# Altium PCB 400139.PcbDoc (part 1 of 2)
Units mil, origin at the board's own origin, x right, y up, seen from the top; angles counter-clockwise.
Board outline 2800 x 2160 mil, 2 copper layers (Top Layer, Bottom Layer), stack 61.8 mil thick; 154 components, 167 nets, 587 pads, 544 vias.
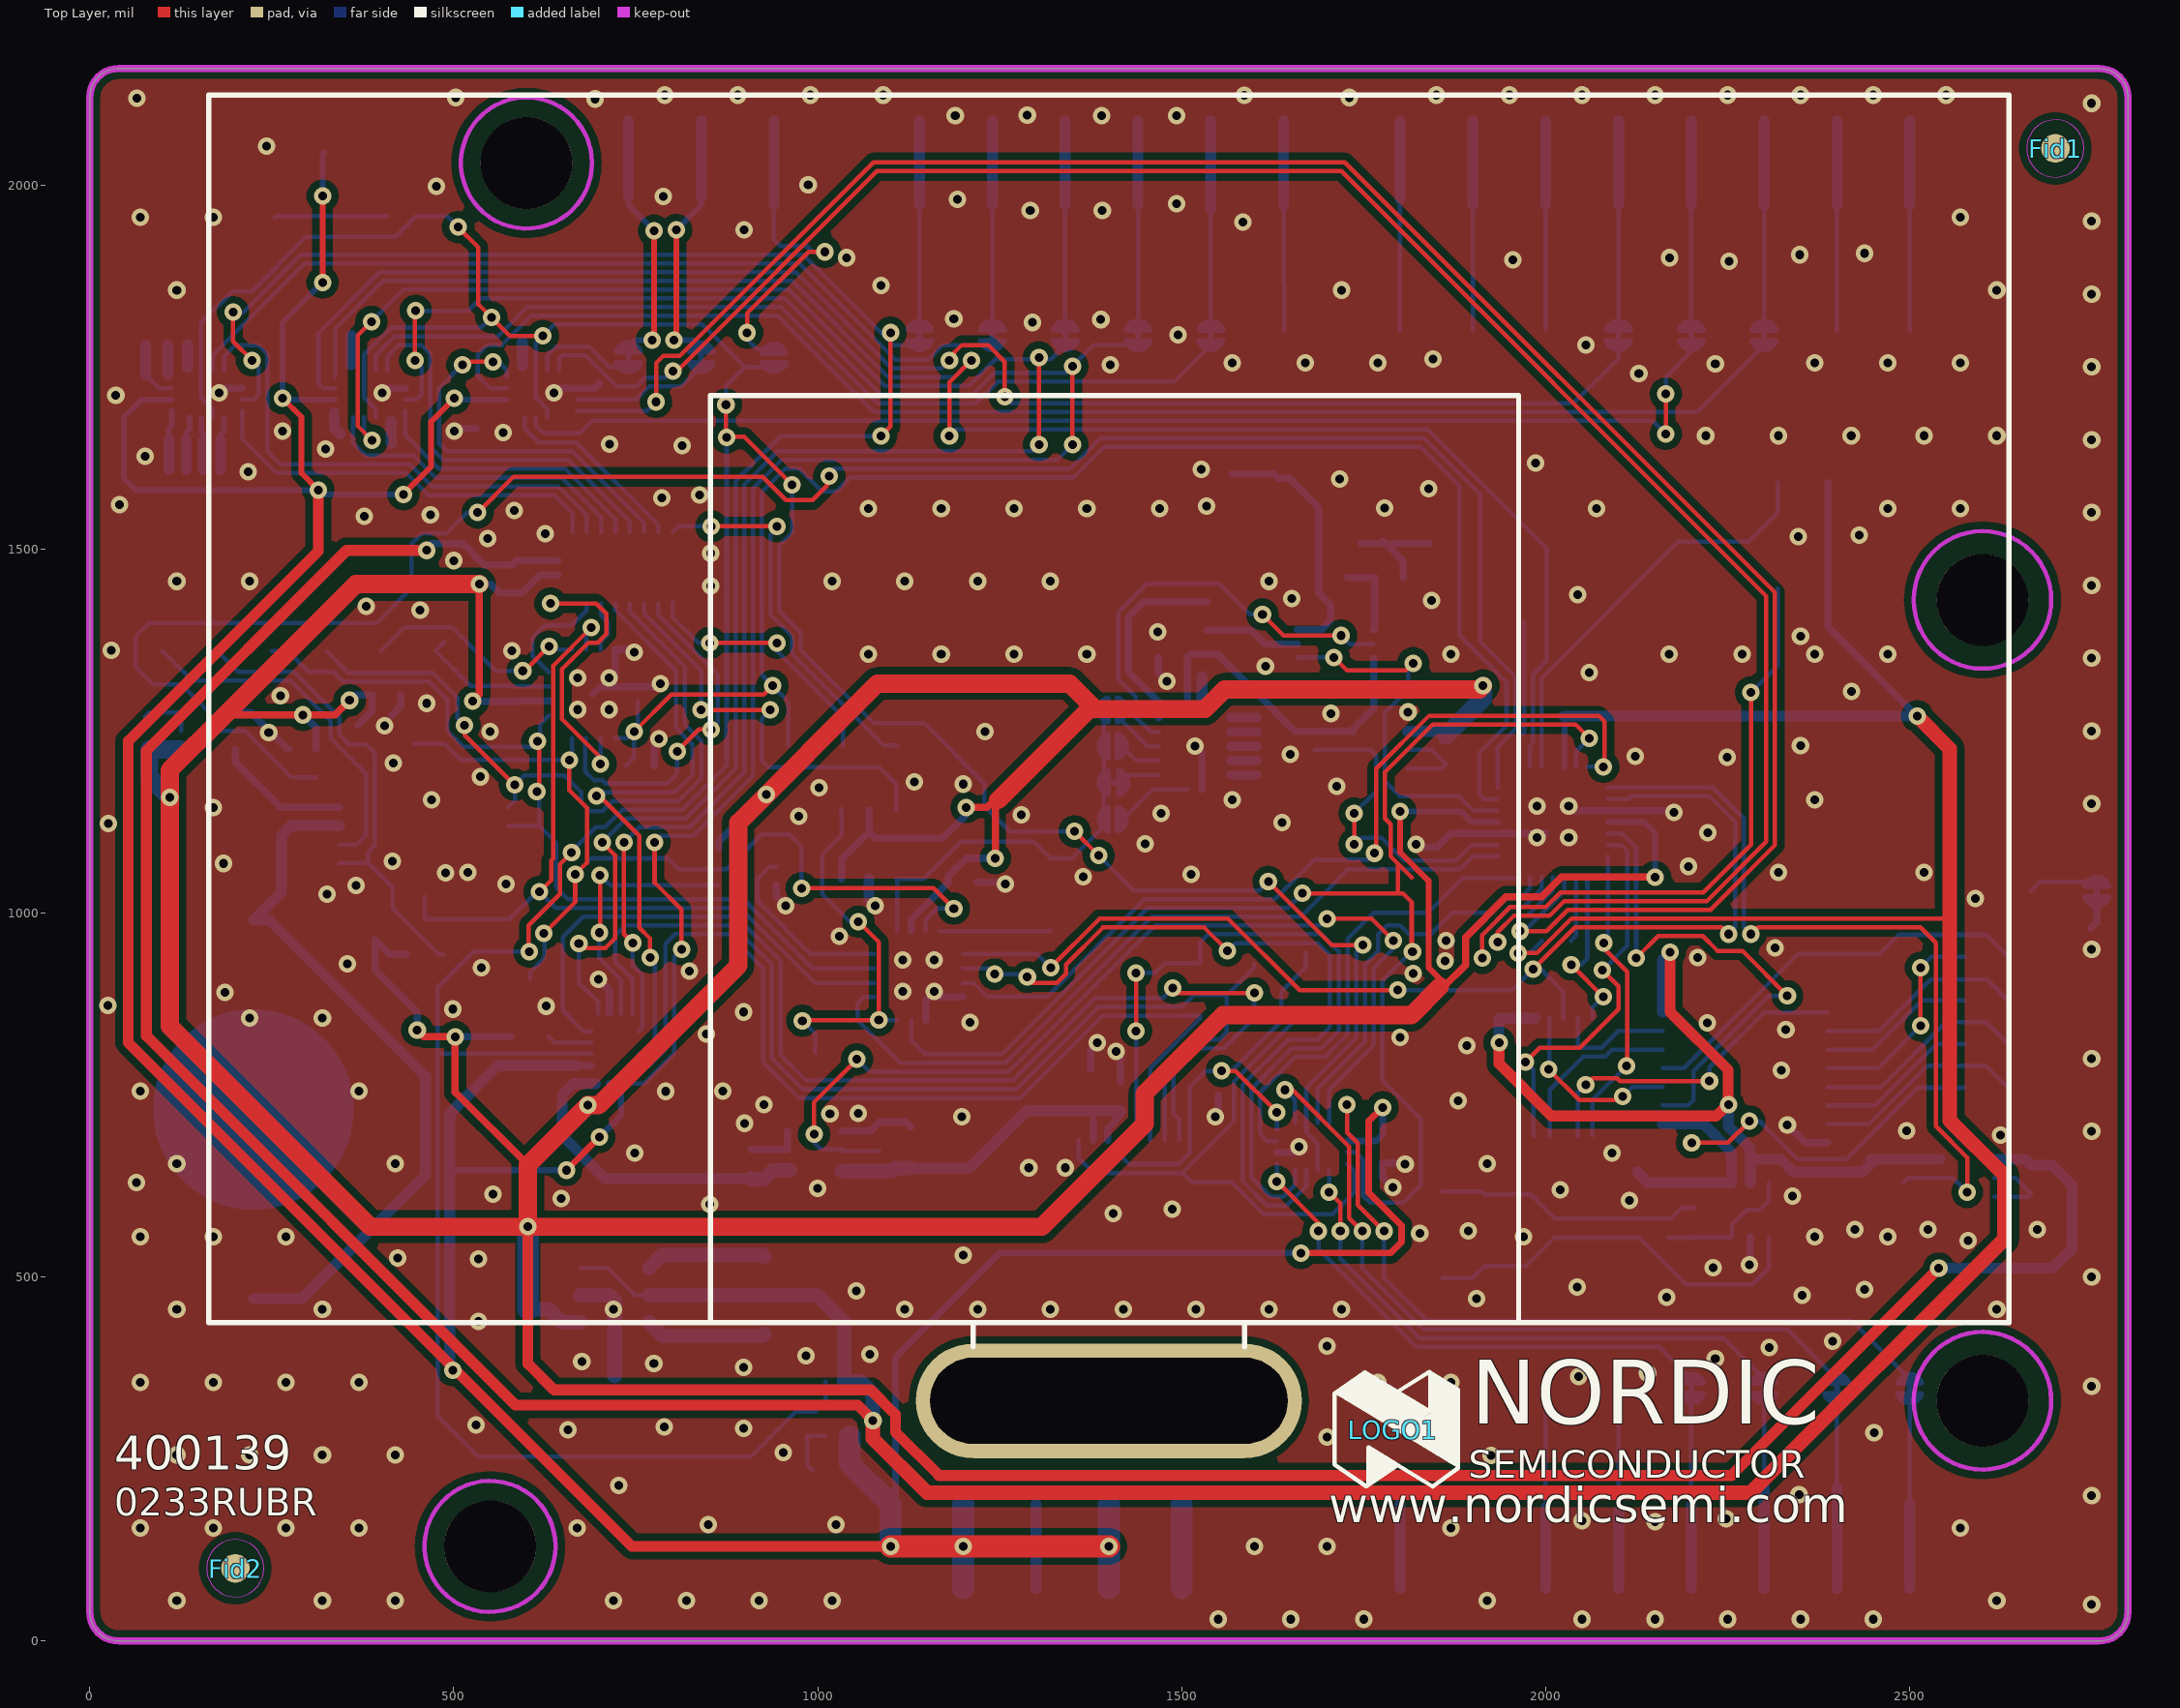
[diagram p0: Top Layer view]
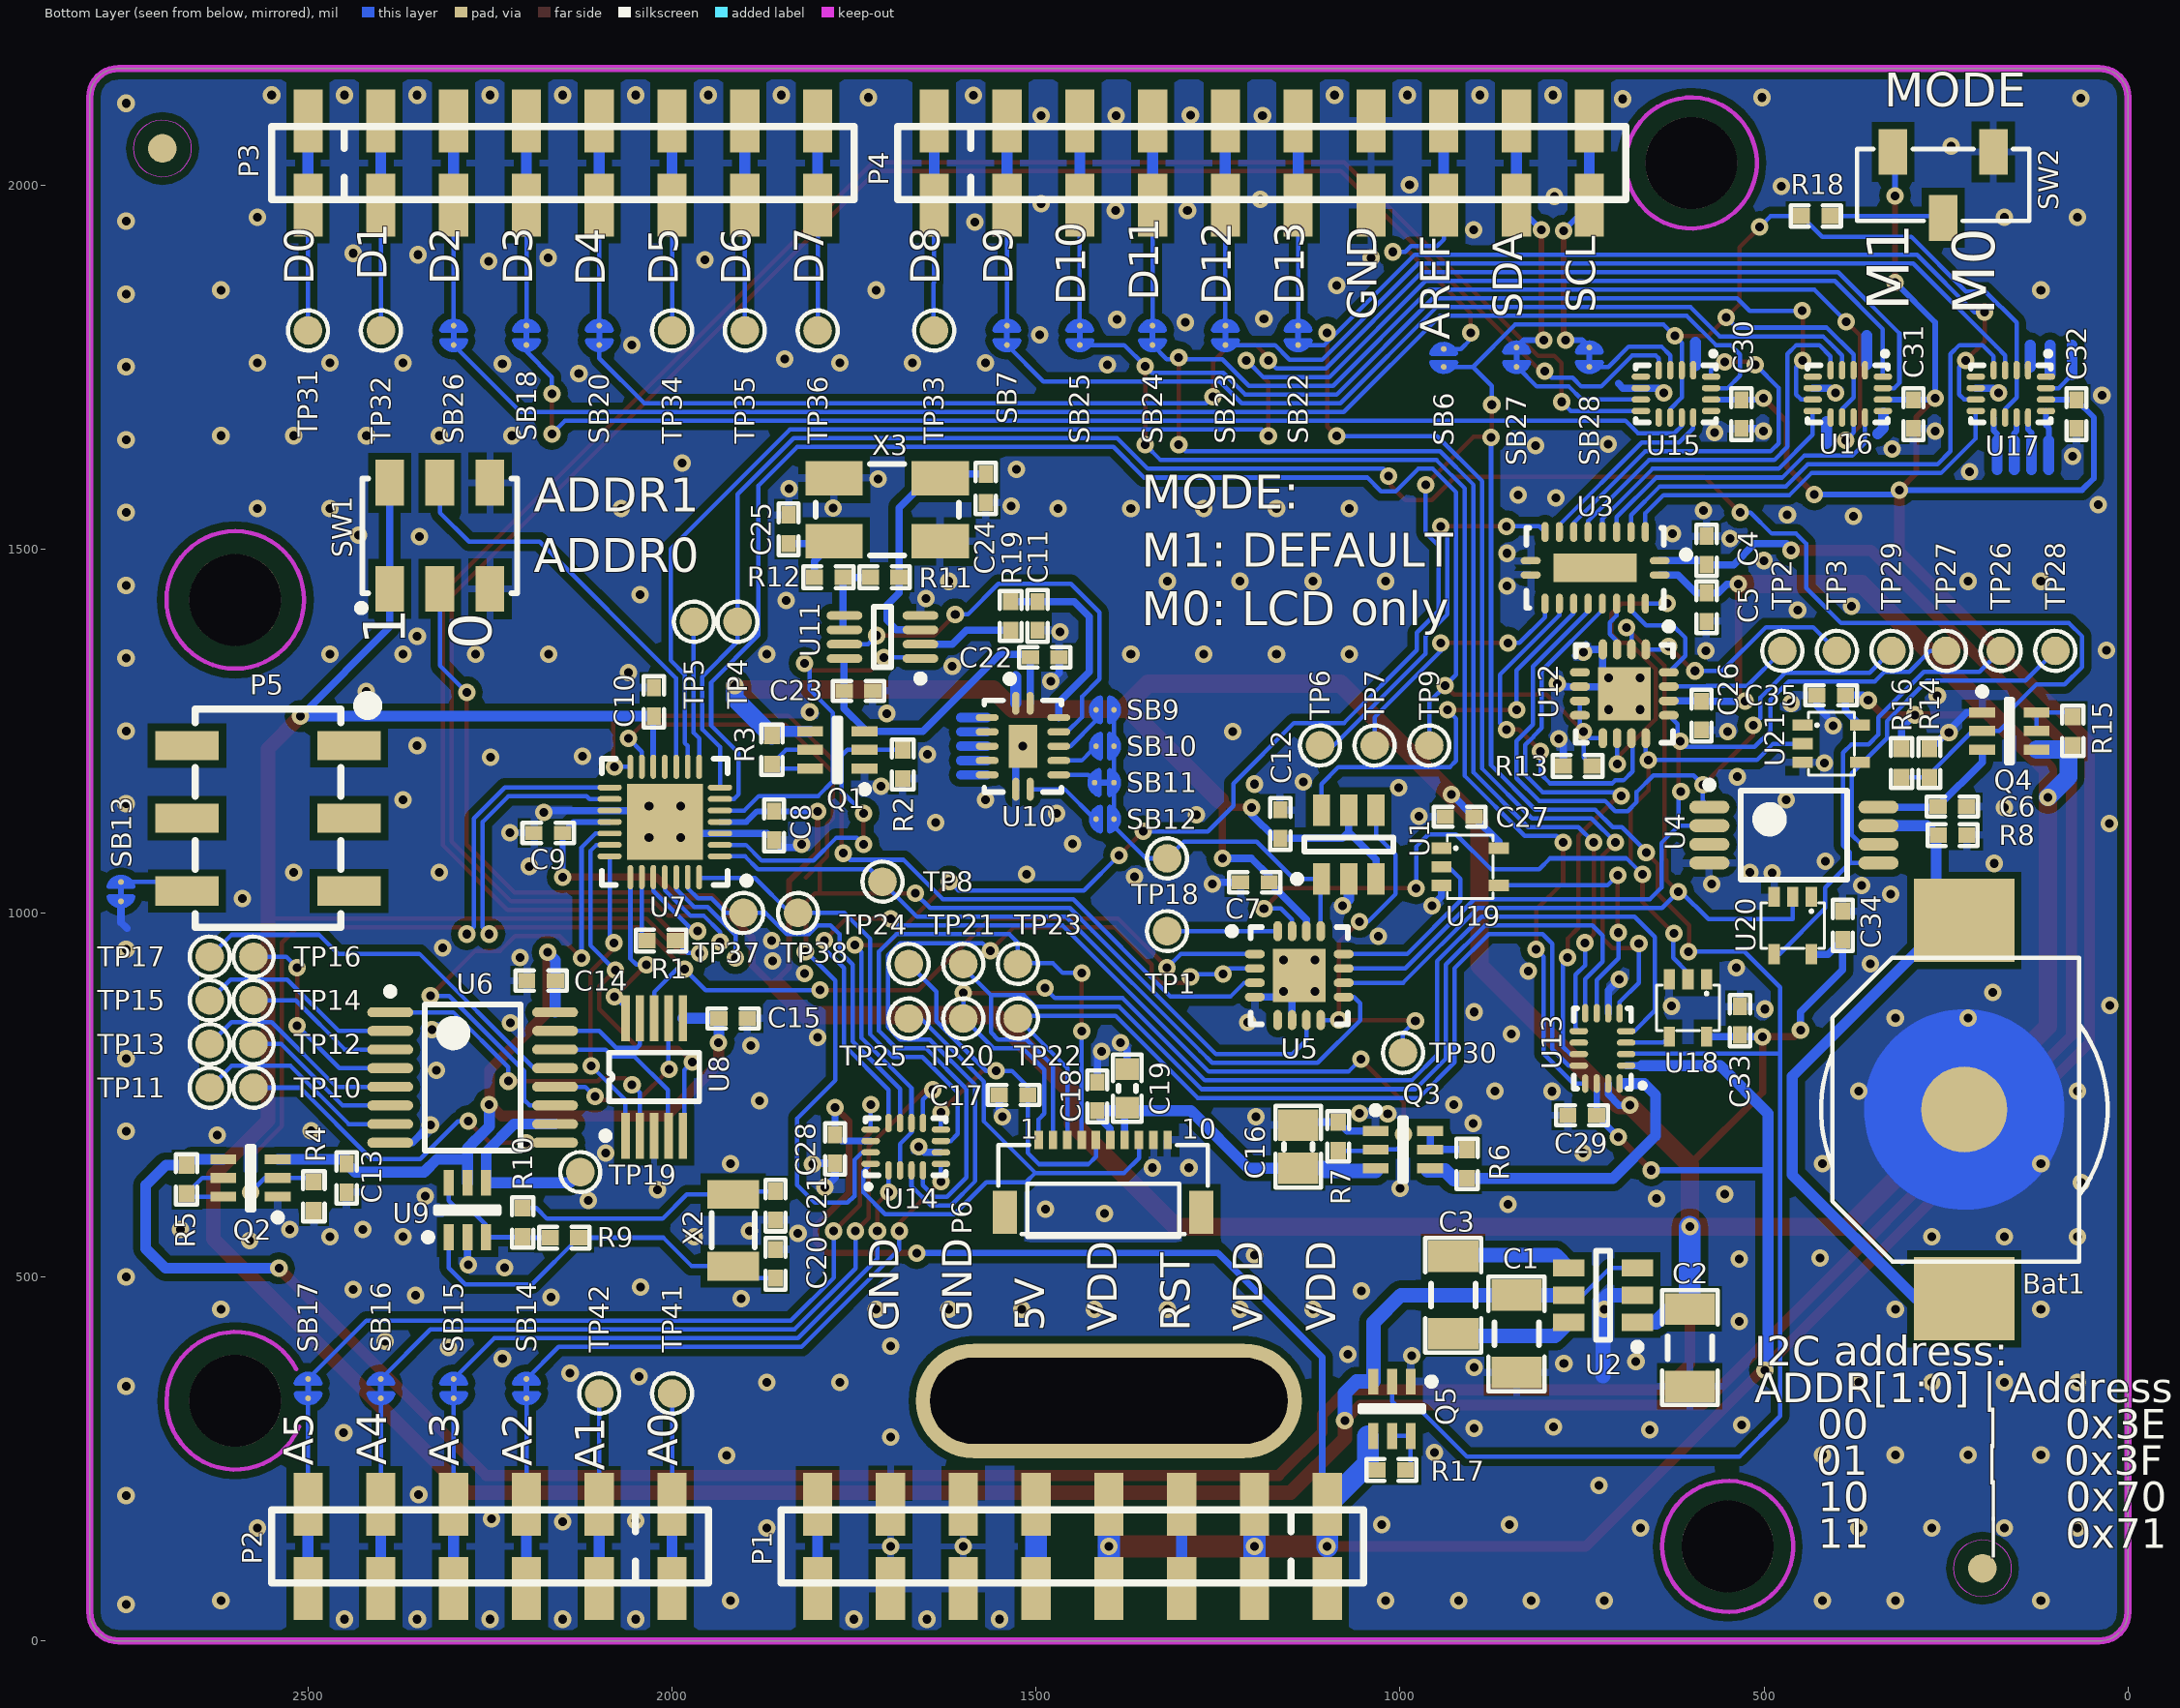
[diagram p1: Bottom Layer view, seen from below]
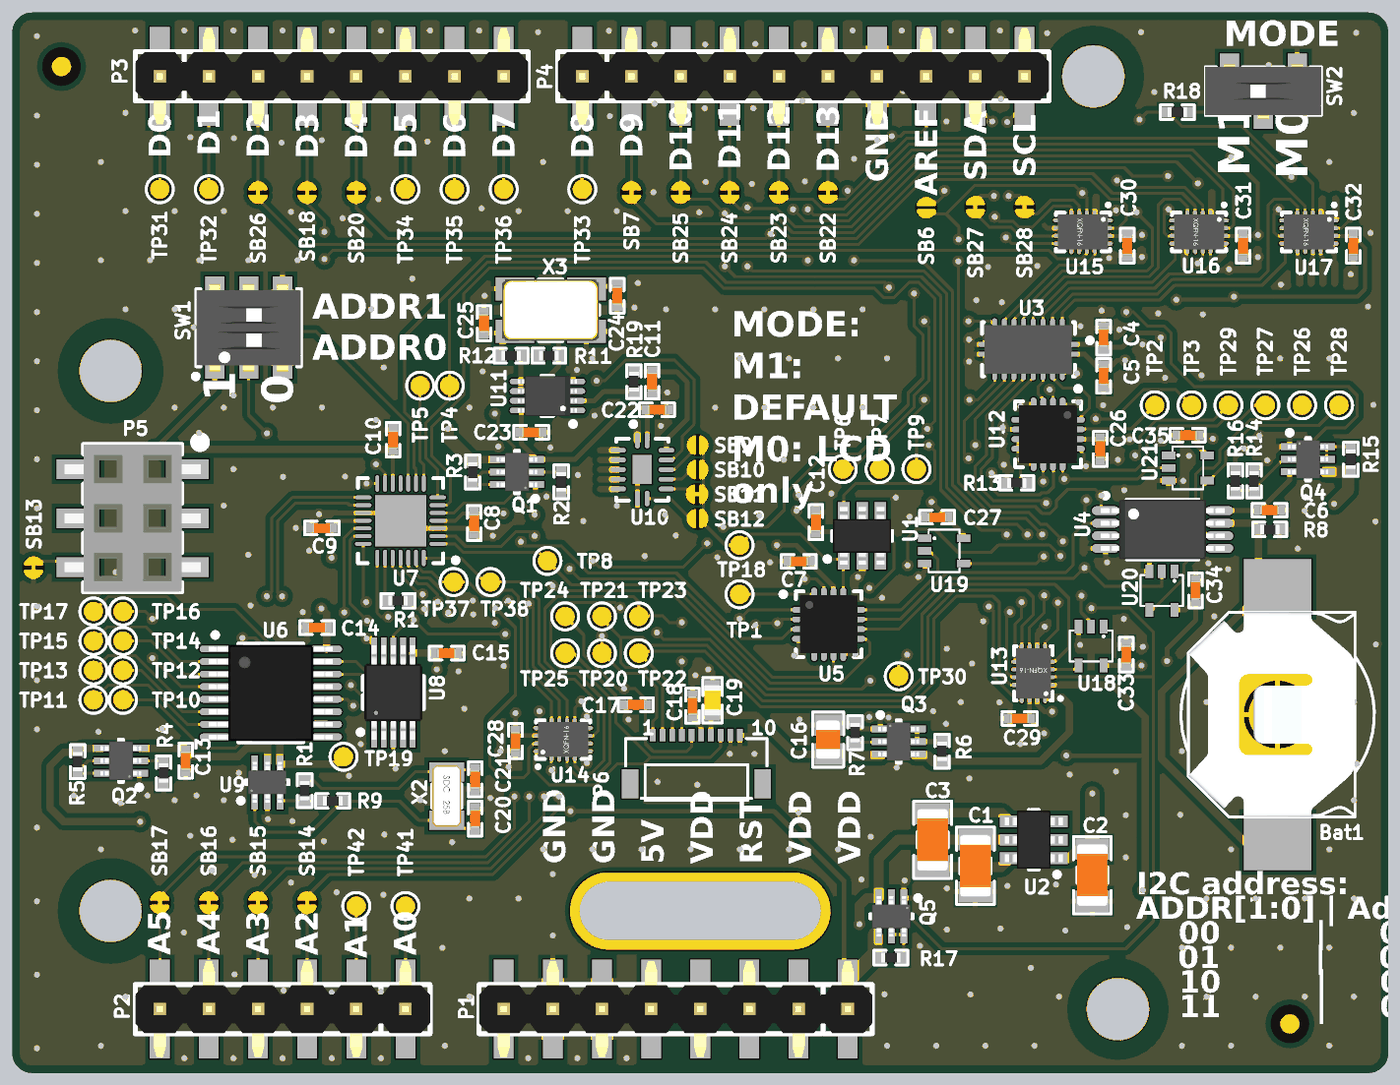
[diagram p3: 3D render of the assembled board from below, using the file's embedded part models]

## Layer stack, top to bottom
Top Solder: solder mask 0.4, Solder Resist, Dk 3.5
Top Layer: signal copper 1.4
Dielectric1: core 59, FR-4, Dk 4.4
Bottom Layer: signal copper 1.4
Bottom Solder: solder mask 0.4, Solder Resist, Dk 3.5

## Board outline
0,40 0,2120 0,2120.51 cw(c40,2120) 40.51,2160 40,2160 2760,2160 cw(c2760,2120) 2800,2120 2800,40 2800,40.51 cw(c2760,40) 2760.51,0 2760,0 40,0 cw(c40,40)

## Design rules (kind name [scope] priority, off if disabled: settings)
Clearance ANT_Clerance [InNet('ANT') or InNet('RF')] p1: gap=5
Clearance Polygon_Clearance [(InNamedPolygon('Top_Layer-GND')) or (InNamedPolygon('Bottom_Layer-GND'))] p2: gap=10
Clearance [All] p3: gap=6
ComponentClearance [All] p1 off: gap=10 collisioncheckmode=3 verticalgap=10 showdistances=FALSE
DiffPairsRouting [All] p1: maxlimit=5.91 minlimit=5.91 mostfreqgap=5.91 toplayer_minwidth=8 toplayer_maxwidth=15 toplayer_prefwidth=15 bottomlayer_minwidth=8 bottomlayer_maxwidth=15 bottomlayer_prefwidth=15 maxuncoupledlength=500
FabricationTestPointUsage TestPointUsage [All] p1: valid=0 allowmultiple=FALSE
FabricationTestpoint Testpoint [All] p1: side=3 testpointundercomponent=TRUE minsize=40 maxsize=100 preferedsize=60 minholesize=0 maxholesize=40 preferedholesize=32 testpointgrid=1 allowsidetop=TRUE allowsidebottom=TRUE usegrid=TRUE gridtolerance=0.01
Height [All] p1 off: minheight=0 maxheight=1000 prefheight=500
HoleSize [All] p1: absolutevalues=TRUE maxlimit=2000 minlimit=12 maxpercent=80.000 minpercent=20.000
MinimumAnnularRing [All] p1 off: minimumring=6
PolygonConnect PolygonConnect_1 [isVia and innet(gnd) or isVia and innet(VIO) or HasFootprint('COAXIAL-SWF')] p1: connectstyle=Direct reliefconductorwidth=10 reliefentries=4 polygonreliefangle="90 Angle" airgapwidth=10
PolygonConnect [All] p2: connectstyle=Relief reliefconductorwidth=10 reliefentries=4 polygonreliefangle="90 Angle" airgapwidth=10
RoutingVias [All] p1: holewidth=12 width=24 viastyle="Through Hole" minholewidth=12 minwidth=24 maxholewidth=28 maxwidth=50
SilkToSolderMaskClearance SilkscreenOverComponentPads [IsPad] p1: minsilkscreentomaskgap=10 clearancetoexposedcopper=TRUE
SolderMaskExpansion [All] p1: expansion=3
Width [All] p1: maxlimit=2000 minlimit=6 preferedwidth=6 minimp=50.000000 maximp=50.000000 favimp=50.000000
23 further rules are at their usual default settings.

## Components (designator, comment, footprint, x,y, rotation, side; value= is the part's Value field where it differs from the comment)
Bat1 "Bat Holder CR1025" CR1025_HOLDER_SMD 225,730 r270 bottom
C1 "2.2µF" CAPC3216X13L 840,422 r90 bottom
C2 "2.2µF" CAPC3216X13L 602,403 r90 bottom
C3 "220nF" CAPC3216X13L 927,475 r270 bottom
C4 "100nF" CAPC1005X04L 579,1498 r270 bottom
C5 "100nF" CAPC1005X04L 579,1420 r90 bottom
C6 "100nF" CAPC1005X04L 241.31,1146.16 r0 bottom
C7 "100nF" CAPC1005X04L 1199.53,1041.98 r180 bottom
C8 "100nF" CAPC1005X04L 1860,1120 r90 bottom
C9 "100nF" CAPC1005X04L 2170,1110 r180 bottom
C10 "100nF" CAPC1005X04L 2025,1290 r270 bottom
C11 "180pF" CAPC1005X04L 1498,1408 r90 bottom
C12 "100nF" CAPC1005X04L 1164.53,1121.98 r270 bottom
C13 "100nF" CAPC1005X04L 2447,636 r90 bottom
C14 "100nF" CAPC1005X04L 2179.95,907.05 r180 bottom
C15 "100nF" CAPC1005X04L 1916,855 r0 bottom
C16 "10µF" CAPC2012X11L 1139.87,679.13 r270 bottom
C17 "100nF" CAPC1005X04L 1531,750 r180 bottom
C18 "100nF" CAPC1005X04L 1415.87,748.09 r270 bottom
C19 "1.0µF" CAPC1608X06L 1374.87,759.09 r270 bottom
C20 "12pF" CAPC1005X04L 1858,518.06 r90 bottom
C21 "12pF" CAPC1005X04L 1858,598.06 r270 bottom
C22 "100nF" CAPC1005X04L 1488,1351 r0 bottom
C23 "100nF" CAPC1005X04L 1744,1305 r0 bottom
C24 "18pF" CAPC1005X04L 1569,1583 r270 bottom
C25 "18pF" CAPC1005X04L 1840,1527 r90 bottom
C26 "100nF" CAPC1005X04L 586,1271 r90 bottom
C27 "100nF" CAPC1005X04L 918,1132 r0 bottom
C28 "100nF" CAPC1005X04L 1776,676 r90 bottom
C29 "100nF" CAPC1005X04L 750,722 r180 bottom
C30 "100nF" CAPC1005X04L 531,1685 r90 bottom
C31 "100nF" CAPC1005X04L 295,1685 r90 bottom
C32 "100nF" CAPC1005X04L 71,1685 r90 bottom
C33 "100nF" CAPC1005X04L 533,852 r90 bottom
C34 "100nF" CAPC1005X04L 392,983 r90 bottom
C35 "100nF" CAPC1005X04L 408,1299 r0 bottom
Fid1 "Fiducial mark" Fiducial 2700,2050 r180 top
Fid2 "Fiducial mark" Fiducial 200,100 r0 top
LOGO1 "Nordic Logo M" NORDIC_LOGO_M 1790,290 r0 top
P1 "Pin List 1x8" LIST_1x8_SMD 1100,130 r0 bottom locked
P2 "Pin List 1x6" LIST_1x6_SMD 2000,130 r0 bottom locked
P3 "Pin List 1x8" LIST_1x8_SMD 2500,2030 r180 bottom locked
P4 "Pin List 1x10" LIST_1x10_SMD 1640,2030 r180 bottom locked
P5 "Socket 2x3" SOCKET_2x3_SMD-2.54mm-bottom 2555,1130 r270 top locked
P6 "FPC-10-0.5mm" "Molex 51441-1072" 1407.87,688.09 r0 bottom locked
Q1 "FDG6321C" SOT65P210X100-6N 1773,1224 r0 bottom
Q2 "FDG6321C" SOT65P210X100-6N 2579,636 r0 bottom
Q3 "FDG6321C" SOT65P210X100-6N 996.12,675 r180 bottom
Q4 "FDG6321C" SOT65P210X100-6N 163,1250 r180 bottom
Q5 "FDG6321C" SOT65P210X100-6N 1011,319 r270 bottom
R1 "10k" RESC1005X04L 2015,962 r180 bottom
R2 "N.C." RESC1005X04L 1683,1204 r270 bottom
R3 "1M0" RESC1005X04L 1863,1224 r270 bottom
R4 "N.C." RESC1005X04L 2492,611 r270 bottom
R5 "1M0" RESC1005X04L 2667,634 r270 bottom
R6 "1M0" RESC1005X04L 907.87,655.13 r90 bottom
R7 "N.C." RESC1005X04L 1084.87,693.13 r90 bottom
R8 "N.C." RESC1005X04L 241,1107 r0 bottom
R9 "10M" RESC1005X04L 2148,554 r0 bottom
R10 "330k" RESC1005X04L 2205,575.06 r270 bottom
R11 "1M0" RESC1005X04L 1708,1461 r0 bottom
R12 "1k" RESC1005X04L 1785,1461 r180 bottom
R13 "1M0" RESC1005X04L 756,1202 r180 bottom
R14 "N.C." RESC1005X04L 273,1206 r90 bottom
R15 "1M0" RESC1005X04L 76,1250 r90 bottom
R16 "1M0" RESC1005X04L 311,1206 r270 bottom
R17 "1M0" RESC1005X04L 1012,235 r180 bottom
R18 "10k" RESC1005X04L 429,1957 r180 bottom
R19 "100R" RESC1005X04L 1535,1408 r90 bottom
SB6 "Solderbridge" Solderbridge#1 940,1750 r90 bottom
SB7 "Solderbridge" Solderbridge_Shorted 1540,1780 r90 bottom net-tie
SB9 "Solderbridge" Solderbridge#2 1393,1279 r0 bottom
SB10 "Solderbridge" Solderbridge#2 1393,1229 r0 bottom
SB11 "Solderbridge" Solderbridge_Shorted 1393,1179 r0 bottom net-tie
SB12 "Solderbridge" Solderbridge#3 1393,1129 r0 bottom
SB13 "Solderbridge" Solderbridge_Shorted 2757,1016 r90 bottom net-tie
SB14 "Solderbridge" Solderbridge_Shorted 2200,360 r270 bottom net-tie
SB15 "Solderbridge" Solderbridge_Shorted 2300,360 r270 bottom net-tie
SB16 "Solderbridge" Solderbridge_Shorted 2400,360 r270 bottom net-tie
SB17 "Solderbridge" Solderbridge_Shorted 2500,360 r270 bottom net-tie
SB18 "Solderbridge" Solderbridge_Shorted 2200,1780 r90 bottom net-tie
SB20 "Solderbridge" Solderbridge_Shorted 2100,1780 r90 bottom net-tie
SB22 "Solderbridge" Solderbridge_Shorted 1140,1780 r90 bottom net-tie
SB23 "Solderbridge" Solderbridge_Shorted 1240,1780 r90 bottom net-tie
SB24 "Solderbridge" Solderbridge_Shorted 1340,1780 r90 bottom net-tie
SB25 "Solderbridge" Solderbridge_Shorted 1440,1780 r90 bottom net-tie
SB26 "Solderbridge" Solderbridge_Shorted 2300,1780 r90 bottom net-tie
SB27 "Solderbridge" Solderbridge_Shorted 840,1750 r90 bottom net-tie
SB28 "Solderbridge" Solderbridge_Shorted 740,1750 r90 bottom net-tie
SW1 "Switch" CAS-D20A 2319,1518 r180 bottom
SW2 "Switch" CJS-120xA 254,2000 r0 bottom
TP1 "Ø1.0mm,SMD" TP_SMD_Ø1.0mm#1 1320,975 r180 bottom
TP2 "Ø1.0mm,SMD" TP_SMD_Ø1.0mm#1 475,1360 r180 bottom
TP3 "Ø1.0mm,SMD" TP_SMD_Ø1.0mm#1 400,1360 r180 bottom
TP4 "Ø1.0mm,SMD" TP_SMD_Ø1.0mm#1 1910,1400 r180 bottom
TP5 "Ø1.0mm,SMD" TP_SMD_Ø1.0mm#1 1970,1400 r180 bottom
TP6 "Ø1.0mm,SMD" TP_SMD_Ø1.0mm#1 1110,1230 r180 bottom
TP7 "Ø1.0mm,SMD" TP_SMD_Ø1.0mm#1 1035,1230 r180 bottom
TP8 "Ø1.0mm,SMD" TP_SMD_Ø1.0mm#1 1711,1043 r180 bottom
TP9 "Ø1.0mm,SMD" TP_SMD_Ø1.0mm#1 960,1230 r180 bottom
TP10 "Ø1.0mm,SMD" TP_SMD_Ø1.0mm#1 2575,760 r180 bottom
TP11 "Ø1.0mm,SMD" TP_SMD_Ø1.0mm#1 2635,760 r180 bottom
TP12 "Ø1.0mm,SMD" TP_SMD_Ø1.0mm#1 2575,820 r180 bottom
TP13 "Ø1.0mm,SMD" TP_SMD_Ø1.0mm#1 2635,820 r180 bottom
TP14 "Ø1.0mm,SMD" TP_SMD_Ø1.0mm#1 2575,880 r180 bottom
TP15 "Ø1.0mm,SMD" TP_SMD_Ø1.0mm#1 2635,880 r180 bottom
TP16 "Ø1.0mm,SMD" TP_SMD_Ø1.0mm#1 2575,940 r180 bottom
TP17 "Ø1.0mm,SMD" TP_SMD_Ø1.0mm#1 2635,940 r180 bottom
TP18 "Ø1.0mm,SMD" TP_SMD_Ø1.0mm#1 1320,1075 r180 bottom
TP19 "Ø1.0mm,SMD" TP_SMD_Ø1.0mm#1 2126,644.06 r180 bottom
TP20 "Ø1.0mm,SMD" TP_SMD_Ø1.0mm#1 1600,855 r180 bottom
TP21 "Ø1.0mm,SMD" TP_SMD_Ø1.0mm#1 1600,930 r180 bottom
TP22 "Ø1.0mm,SMD" TP_SMD_Ø1.0mm#1 1525,855 r180 bottom
TP23 "Ø1.0mm,SMD" TP_SMD_Ø1.0mm#1 1525,930 r180 bottom
TP24 "Ø1.0mm,SMD" TP_SMD_Ø1.0mm#1 1675,930 r180 bottom
TP25 "Ø1.0mm,SMD" TP_SMD_Ø1.0mm#1 1675,855 r180 bottom
TP26 "Ø1.0mm,SMD" TP_SMD_Ø1.0mm#2 150,1360 r180 bottom
TP27 "Ø1.0mm,SMD" TP_SMD_Ø1.0mm#1 250,1360 r180 bottom
TP28 "Ø1.0mm,SMD" TP_SMD_Ø1.0mm#1 100,1360 r180 bottom
TP29 "Ø1.0mm,SMD" TP_SMD_Ø1.0mm#1 325,1360 r180 bottom
TP30 "Ø1.0mm,SMD" TP_SMD_Ø1.0mm#1 996,808 r180 bottom
TP31 "Ø1.0mm,SMD" TP_SMD_Ø1.0mm#1 2500,1800 r180 bottom
TP32 "Ø1.0mm,SMD" TP_SMD_Ø1.0mm#1 2400,1800 r180 bottom
TP33 "Ø1.0mm,SMD" TP_SMD_Ø1.0mm#1 1640,1800 r180 bottom
TP34 "Ø1.0mm,SMD" TP_SMD_Ø1.0mm#1 2000,1800 r180 bottom
TP35 "Ø1.0mm,SMD" TP_SMD_Ø1.0mm#1 1900,1800 r180 bottom
TP36 "Ø1.0mm,SMD" TP_SMD_Ø1.0mm#1 1800,1800 r180 bottom
TP37 "Ø1.0mm,SMD" TP_SMD_Ø1.0mm#1 1902,1000 r180 bottom
TP38 "Ø1.0mm,SMD" TP_SMD_Ø1.0mm#1 1827,1000 r180 bottom
TP41 "Ø1.0mm,SMD" TP_SMD_Ø1.0mm#1 2000,340 r180 bottom
TP42 "Ø1.0mm,SMD" TP_SMD_Ø1.0mm#1 2100,340 r180 bottom
U1 "SN74LVC1G175" SOT95P280X145-6N 1070.53,1093.98 r90 bottom
U2 "REG710NA-3.3" SOT95P280X145-6N 721.16,475 r0 bottom
U3 "FXMA108" QFN50P450X250X80_HS-21N 732,1474 r270 bottom
U4 "23LCV512" TSOP65P640X120-8N 459,1107 r180 bottom
U5 "NX3L4053" QFN50P300X300X50_HS-17N 1138.53,913.98 r180 bottom
U6 "74VHC4040FT" TSOP65P640X110-16N 2273.95,774.05 r180 bottom
U7 "SX1509BIULTRT" QFN40P400X400X60_HS-29N 2010,1125 r0 bottom
U8 "ADG704" MSOP-10 2063.95,694.05 r180 bottom
U9 "74LVC2GU04" SOT65P210X100-6N 2281,592.06 r90 bottom
U10 "74HC393BQ" QFN50P250X300X100_HS-15N 1518,1229 r180 bottom
U11 "74LVC3GU04DC" TSSOP50P310X90-8N 1711,1379 r0 bottom
U12 "NX3L4053" QFN50P300X300X50_HS-17N 692,1301 r270 bottom
U13 "NX3DV2567" XQFN40P180X260X50-16N 722,814 r0 bottom
U14 "FSA2466UMX" XQFN40P180X260X50-16N 1679,679 r90 bottom
U15 "FSA2466UMX" XQFN40P180X260X50-16N 621,1713 r270 bottom
U16 "FSA2466UMX" XQFN40P180X260X50-16N 385,1713 r270 bottom
U17 "FSA2466UMX" XQFN40P180X260X50-16N 161,1713 r270 bottom
U18 "74LVC1G17" SOT-353 579,909 r0 bottom
U19 "74LVC1G17" SOT-353 943,1089 r270 bottom
U20 "74LVC1G17" SOT-353 435,1022 r0 bottom
U21 "74LVC1G17" SOT-353 447,1258 r270 bottom
X2 "32.768kHz" XTAL_3215 1916,564.06 r270 bottom
X3 "8MHz" BT-XTAL_5032 1704.47,1553.75 r0 bottom

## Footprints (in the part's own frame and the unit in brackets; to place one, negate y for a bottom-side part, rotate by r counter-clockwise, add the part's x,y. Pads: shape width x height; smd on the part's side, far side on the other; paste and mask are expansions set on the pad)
BT-XTAL_5032 [mm] "Abracon ABM3B Series 5.0mmx3.2mm SMD"
  rect 2x1.2 smd: 1(-1.85,-1.1) 2(1.85,-1.1) 3(1.85,1.1) 4(-1.85,1.1)
  silkscreen extent -2.5,-1.6 2.5,1.6, body extent -2.5,-1.6 2.5,1.6, height 1
CAPC1005X04L [mm] "Chip Capacitor, 2-Leads, Body 1.0x0.5mm, IPC High Density"
  rect 0.6x0.5 smd: 1(-0.5,0) 2(0.5,0)
  silkscreen extent -0.9,-0.35 0.9,0.35, body extent -0.51,-0.25 0.51,0.25, height 0.5
CAPC1608X06L [mm] "Chip Capacitor, 2-Leads, Body 1.6x0.8mm, IPC High Density"
  rect 0.75x0.8 smd: 1(-0.675,0) 2(0.675,0)
  silkscreen extent -1.17,-0.5 1.17,0.5, body extent -0.8,-0.43 0.8,0.43, height 0.8
CAPC2012X11L [mm] "Chip Capacitor, 2-Leads, Body 2.0x1.3mm, IPC High Density"
  rect 1.1x1.4 smd: 1(-0.75,0) 2(0.75,0)
  silkscreen extent -1.43,-0.8 1.42,0.8, body extent -1,-0.62 1,0.63, height 0.77
CAPC3216X13L [mm] "Chip Capacitor, 2-Leads, Body 3.2x1.6mm, IPC High Density"
  rect 1.1x1.75 smd: 1(-1.35,0) 2(1.35,0)
  silkscreen extent -2,-0.97 2,0.97, body extent -1.6,-0.8 1.6,0.8, height 0.99
CAS-D20A [mm] "SLIDE SWITCH 2xSPDT J HOOK"
  rect 1x1.6 smd: 1(-1.75,-1.85) 2(0,-1.85) 3(1.75,-1.85) 4(-1.75,1.85) 5(0,1.85) 6(1.75,1.85)
  silkscreen extent -2.84,-2.62 2.7,2, body extent -2.7,-2.27 2.7,2.28, height 2.5
CJS-120xA [mm] "Slide Switches - SPDT, SMD, ON-ON"
  rect 1x1.6 smd: 1(1.75,-1.15) 2(0,1.15) 3(-1.75,-1.15)
  silkscreen extent -3,-1.25 3,1.25, body extent -3,-1.4 3,1.45, height 2.5
CR1025_HOLDER_SMD [mm] "CR1025 battery retainer SMD"
  round 7 on Bottom Solder paste+0: 0(0,0)
  rect 2.9x3.5 smd: 1(-6.6,0) 1(6.6,0)
  round 3 smd paste-8: 2(0,0)
  Top Layer circle w5: c0,0 r1
  silkscreen extent -5.3,-5 5.3,5, body extent -8.05,-4.61 8.05,4, height 1.95
Fiducial [mm] "Fiducial Mark"
  round 1 smd paste-10 mask+0.5: 0(0,0)
  round 1 smd far side paste-10 mask+0.5: 0(0,0)
  Keep-Out Layer circle w0.01: c0,0 r1
LIST_1x6_SMD [mm] "Pin List, 2.54mm, SMD"
  rect 1.02x2.19 smd: 1(0,-1.465) 1(0,1.465) 2(2.54,-1.465) 2(2.54,1.465) 3(5.08,-1.465) 3(5.08,1.465) 4(7.62,-1.465) 4(7.62,1.465) 5(10.16,-1.465) 5(10.16,1.465) 6(12.7,-1.465) 6(12.7,1.465)
  silkscreen extent -1.27,-1.27 13.97,1.27, body extent -1.27,-2.5 13.97,2.5, height 9.82
LIST_1x8_SMD [mm] "Pin List, 2.54mm, SMD"
  rect 1.02x2.19 smd: 1(0,-1.465) 1(0,1.465) 2(2.54,-1.465) 2(2.54,1.465) 3(5.08,-1.465) 3(5.08,1.465) 4(7.62,-1.465) 4(7.62,1.465) 5(10.16,-1.465) 5(10.16,1.465) 6(12.7,-1.465) 6(12.7,1.465) 7(15.24,-1.465) 7(15.24,1.465) 8(17.78,-1.465) 8(17.78,1.465)
  silkscreen extent -1.27,-1.27 19.05,1.27, body extent -1.27,-2.5 19.05,2.5, height 9.82
LIST_1x10_SMD [mm] "Pin List, 2.54mm, SMD"
  rect 1.02x2.19 smd: 1(0,-1.465) 1(0,1.465) 2(2.54,-1.465) 2(2.54,1.465) 3(5.08,-1.465) 3(5.08,1.465) 4(7.62,-1.465) 4(7.62,1.465) 5(10.16,-1.465) 5(10.16,1.465) 6(12.7,-1.465) 6(12.7,1.465) 7(15.24,-1.465) 7(15.24,1.465) 8(17.78,-1.465) 8(17.78,1.465) 9(20.32,-1.465) 9(20.32,1.465) 10(22.86,-1.465) 10(22.86,1.465)
  silkscreen extent -1.27,-1.27 24.13,1.27, body extent -1.27,-2.5 24.13,2.5, height 9.82
"Molex 51441-1072" [mm] "Connector, FPC, SMD, 0.5mm, 10-way"
  rect 0.3x0.65 smd mask+0.076: 1(2.25,0) 2(1.75,0) 3(1.25,0) 4(0.75,0) 5(0.25,0) 6(-0.25,0) 7(-0.75,0) 8(-1.25,0) 9(-1.75,0) 10(-2.25,0)
  rect 0.85x1.5 smd: ""(-3.425,2.525) ""(3.425,2.525)
  silkscreen extent -3.65,0.18 3.65,3.37
MSOP-10 [mm] "Shrink Small Outline; 10 Leads; Body Width 3 mm; Pitch 0.5 mm"
  rect 0.3x1.6 smd: 1(0,0) 2(0.5,0) 3(1,0) 4(1.5,0) 5(2,0) 6(2,4.1) 7(1.5,4.1) 8(1,4.1) 9(0.5,4.1) 10(0,4.1)
  silkscreen extent -0.83,-0.12 2.58,2.9, body extent -0.5,-0.4 2.5,4.5, height 1.15
NORDIC_LOGO_M [mil] "Medium Nordic Logo"
  silkscreen extent -80,-78 90,80
QFN40P400X400X60_HS-29N [mm] "QFN, 28-Leads, Body 4,00x4,00mm, Pitch 0,40mm, Thermal Pad 2,65x2,65mm, IPC Medium Density"
  oval 0.85x0.2 smd: 1(-1.925,1.2) 2(-1.925,0.8) 3(-1.925,0.4) 4(-1.925,0) 5(-1.925,-0.4) 6(-1.925,-0.8) 7(-1.925,-1.2) 15(1.925,-1.2) 16(1.925,-0.8) 17(1.925,-0.4) 18(1.925,0) 19(1.925,0.4) 20(1.925,0.8) 21(1.925,1.2)
  oval 0.2x0.85 smd: 8(-1.2,-1.925) 9(-0.8,-1.925) 10(-0.4,-1.925) 11(0,-1.925) 12(0.4,-1.925) 13(0.8,-1.925) 14(1.2,-1.925) 22(1.2,1.925) 23(0.8,1.925) 24(0.4,1.925) 25(0,1.925) 26(-0.4,1.925) 27(-0.8,1.925) 28(-1.2,1.925)
  rect 2.65x2.65 smd: 29(0,0)
  silkscreen extent -2.97,-2.2 2.2,2.2, body extent -2.05,-2.05 2.05,2.05, height 0.6
QFN50P250X300X100_HS-15N [mm] "QFN, 14-Leads, Body 2.50x3.00mm, Pitch 0.50mm, Thermal Pad 1.00x1.50mm, IPC Medium Density"
  oval 0.25x0.8 smd: 1(-0.25,1.5) 7(-0.25,-1.5) 8(0.25,-1.5) 14(0.25,1.5)
  oval 0.8x0.25 smd: 2(-1.25,1) 3(-1.25,0.5) 4(-1.25,0) 5(-1.25,-0.5) 6(-1.25,-1) 9(1.25,-1) 10(1.25,-0.5) 11(1.25,0) 12(1.25,0.5) 13(1.25,1)
  rect 1x1.5 smd: 15(0,0)
  silkscreen extent -1.35,-1.6 1.35,2.47, body extent -1.3,-1.55 1.3,1.55, height 1
QFN50P300X300X50_HS-17N [mm] "QFN, 16-Leads, Body 3.00x3.00mm, Pitch 0.50mm, Thermal Pad 1.85x1.85mm, IPC Medium Density"
  oval 0.7x0.3 smd: 1(-1.55,0.75) 2(-1.55,0.25) 3(-1.55,-0.25) 4(-1.55,-0.75) 9(1.55,-0.75) 10(1.55,-0.25) 11(1.55,0.25) 12(1.55,0.75)
  oval 0.3x0.7 smd: 5(-0.75,-1.55) 6(-0.25,-1.55) 7(0.25,-1.55) 8(0.75,-1.55) 13(0.75,1.55) 14(0.25,1.55) 15(-0.25,1.55) 16(-0.75,1.55)
  rect 1.85x1.85 smd: 17(0,0)
  silkscreen extent -2.48,-1.7 1.7,1.7, body extent -1.5,-1.5 1.5,1.5, height 0.9
QFN50P450X250X80_HS-21N [mm] "QFN, 20-Leads, Body 4.50x2.50mm, Pitch 0.50mm, Thermal Pad 3.15x1.15mm, IPC Medium Density"
  oval 0.25x0.7 smd: 1(-0.25,2.25) 10(-0.25,-2.25) 11(0.25,-2.25) 20(0.25,2.25)
  oval 0.7x0.25 smd: 2(-1.25,1.75) 3(-1.25,1.25) 4(-1.25,0.75) 5(-1.25,0.25) 6(-1.25,-0.25) 7(-1.25,-0.75) 8(-1.25,-1.25) 9(-1.25,-1.75) 12(1.25,-1.75) 13(1.25,-1.25) 14(1.25,-0.75) 15(1.25,-0.25) 16(1.25,0.25) 17(1.25,0.75) 18(1.25,1.25) 19(1.25,1.75)
  rect 1x2.9 smd: 21(0,0)
  silkscreen extent -1.4,-2.4 1.4,3.29, body extent -1.25,-2.27 1.27,2.25, height 1
RESC1005X04L [mm] "Chip Resistor, 2-Leads, Body 1.0x0.5mm, IPC High Density"
  rect 0.6x0.55 smd: 1(-0.5,0) 2(0.5,0)
  silkscreen extent -0.87,-0.38 0.88,0.38, body extent -0.5,-0.25 0.5,0.25, height 0.3
SOCKET_2x3_SMD-2.54mm-bottom [mm] "Socket, 2.54mm, SMD"
  rect 1.02x2.22 smd far side: 1(-2.54,-2.825) 2(-2.54,2.825) 3(0,-2.825) 4(0,2.825) 5(2.54,-2.825) 6(2.54,2.825)
  body extent -3.81,-3.52 3.81,3.52, height 7.47
Solderbridge#1 [mm]
  round 0.2 smd paste-10: 1(0,0) 2(0.625,0)
  Top Layer region: 0.389,0.432 0.465,0.505 0.583,0.467 0.648,0.424 0.721,0.351 0.775,0.292 0.833,0.193 0.861,0.099 0.856,-0.122 0.831,-0.193 0.747,-0.33 0.663,-0.411 0.571,-0.469 0.47,-0.5 0.419,-0.483 0.389,-0.43
  Top Layer region: 0.236,-0.432 0.16,-0.505 0.042,-0.467 -0.023,-0.424 -0.097,-0.351 -0.15,-0.292 -0.208,-0.193 -0.236,-0.099 -0.231,0.122 -0.206,0.193 -0.122,0.33 -0.038,0.411 0.054,0.469 0.155,0.5 0.206,0.483 0.236,0.43
  Top Layer lines w0.152: 0.159,-0.431 cw(c0.27,0) 0,-0.353 cw(c0.27,0) 0.159,0.431 ; 0.465,-0.431 ccw(c0.355,0) 0.625,-0.353 ccw(c0.355,0) 0.465,0.431
Solderbridge#2 [mm]
  round 0.2 smd paste-10: 1(0,0) 2(0.625,0)
  Top Layer region: 0.389,0.432 0.465,0.505 0.583,0.467 0.648,0.424 0.721,0.351 0.775,0.292 0.833,0.193 0.861,0.099 0.856,-0.122 0.831,-0.193 0.747,-0.33 0.663,-0.411 0.571,-0.469 0.47,-0.5 0.419,-0.483 0.389,-0.43
  Top Layer region: 0.236,-0.432 0.16,-0.505 0.042,-0.467 -0.023,-0.424 -0.097,-0.351 -0.15,-0.292 -0.208,-0.193 -0.236,-0.099 -0.231,0.122 -0.206,0.193 -0.122,0.33 -0.038,0.411 0.054,0.469 0.155,0.5 0.206,0.483 0.236,0.43
  Top Layer lines w0.152: 0.159,0.431 ccw(c0.27,0) 0.159,-0.431 ; 0.465,0.431 cw(c0.355,0) 0.465,-0.431
Solderbridge#3 [mm]
  round 0.2 smd paste-10: 1(0,0) 2(0.625,0)
  Top Layer region: 0.389,0.432 0.465,0.505 0.583,0.467 0.648,0.424 0.721,0.351 0.775,0.292 0.833,0.193 0.861,0.099 0.856,-0.122 0.831,-0.193 0.747,-0.33 0.663,-0.411 0.571,-0.469 0.47,-0.5 0.419,-0.483 0.389,-0.43
  Top Layer region: 0.236,-0.432 0.16,-0.505 0.042,-0.467 -0.023,-0.424 -0.097,-0.351 -0.15,-0.292 -0.208,-0.193 -0.236,-0.099 -0.231,0.122 -0.206,0.193 -0.122,0.33 -0.038,0.411 0.054,0.469 0.155,0.5 0.206,0.483 0.236,0.43
  Top Layer lines w0.152: 0.159,0.431 ccw(c0.27,0) 0,0.353 ccw(c0.27,0) -0.052,0.306 ccw(c0.27,0) 0,-0.353 ccw(c0.27,0) 0.159,-0.431 ; 0.465,0.431 cw(c0.355,0) 0.465,-0.431
Solderbridge_Shorted [mm]
  round 0.2 smd paste-10: 1(0,0) 2(0.676,0)
  Top Layer region: 0.236,-0.432 0.16,-0.505 0.042,-0.467 -0.023,-0.424 -0.097,-0.351 -0.15,-0.292 -0.208,-0.193 -0.236,-0.099 -0.231,0.122 -0.206,0.193 -0.122,0.33 -0.038,0.411 0.054,0.469 0.155,0.5 0.206,0.483 0.236,0.43
  Top Layer region: 0.44,0.432 0.516,0.505 0.634,0.467 0.699,0.424 0.772,0.351 0.826,0.292 0.884,0.193 0.912,0.099 0.907,-0.122 0.881,-0.193 0.798,-0.33 0.714,-0.411 0.622,-0.469 0.521,-0.5 0.47,-0.483 0.44,-0.43
  Top Layer lines w0.152: 0.159,-0.431 cw(c0.27,0) 0.159,0.431 ; 0.516,-0.431 ccw(c0.406,0) 0.516,0.431
  Top Layer lines w0.203: 0,0 0.676,0
SOT65P210X100-6N [mm] "SOT23, 6-Leads, Body 2,2x2,4mm (max), Pitch 0,65mm, IPC Medium Density"
  rect 0.9x0.35 smd: 1(-0.95,0.65) 2(-0.95,0) 3(-0.95,-0.65) 4(0.95,-0.65) 5(0.95,0) 6(0.95,0.65)
  silkscreen extent -1.07,-1.1 0.1,1.5, body extent -1.05,-1 1.05,1, height 0.92
SOT95P280X145-6N [mm] "SOT23, 6-Leads, Body 3,1x3,0mm (max), Pitch 0,95mm, IPC Medium Density"
  rect 1.1x0.6 smd: 1(-1.2,0.95) 2(-1.2,0) 3(-1.2,-0.95) 4(1.2,-0.95) 5(1.2,0) 6(1.2,0.95)
  silkscreen extent -1.32,-1.55 0.25,1.93, body extent -1.5,-1.5 1.5,1.5, height 1.45
SOT-353 [mm]
  rect 0.4x0.7 smd: 1(0,0) 2(0.65,0) 3(1.3,0) 4(1.3,2) 5(0,2)
  silkscreen extent -0.45,0.2 1.75,1.8
TP_SMD_Ø1.0mm#1 [mm]
  round 1 smd paste-5: 1(0,0)
  silkscreen extent -0.7,-0.7 0.7,0.7
TP_SMD_Ø1.0mm#2 [mm]
  round 1 smd paste-5: 1(-0.635,0)
  silkscreen extent -1.34,-0.7 0.06,0.7
TSOP65P640X110-16N [mm] "TSOP, 16-Leads, Body 5.00x4.40mm, Pitch 0.65mm, IPC Medium Density"
  oval 1.6x0.35 smd: 1(-2.875,2.275) 2(-2.875,1.625) 3(-2.875,0.975) 4(-2.875,0.325) 5(-2.875,-0.325) 6(-2.875,-0.975) 7(-2.875,-1.625) 8(-2.875,-2.275) 9(2.875,-2.275) 10(2.875,-1.625) 11(2.875,-0.975) 12(2.875,-0.325) 13(2.875,0.325) 14(2.875,0.975) 15(2.875,1.625) 16(2.875,2.275)
  silkscreen extent -3,-2.55 1.68,3.12, body extent -3.2,-2.5 3.2,2.5, height 1
TSOP65P640X120-8N [mm] "TSOP, 8-Leads, Body 3.00x4.40mm, Pitch 0.65mm, IPC Medium Density"
  oval 1.4x0.45 smd: 1(-2.95,0.975) 2(-2.95,0.325) 3(-2.95,-0.325) 4(-2.95,-0.975) 5(2.95,-0.975) 6(2.95,-0.325) 7(2.95,0.325) 8(2.95,0.975)
  silkscreen extent -3.08,-1.55 1.85,1.87, body extent -3.2,-1.55 3.2,1.55, height 1.2
TSSOP50P310X90-8N [mm] "TSSOP, 8-Leads, Body 2,1x2,4mm (max), Pitch 0,50mm, IPC Medium Density"
  oval 1.25x0.3 smd: 1(-1.325,0.75) 2(-1.325,0.25) 3(-1.325,-0.25) 4(-1.325,-0.75) 5(1.325,-0.75) 6(1.325,-0.25) 7(1.325,0.25) 8(1.325,0.75)
  silkscreen extent -1.45,-1.05 0.3,1.57, body extent -1.55,-1.05 1.55,1.05, height 0.8
XQFN40P180X260X50-16N [mm] "QFN, 16-Leads, Body 1.80x2.60mm, Pitch 0.40mm, IPC Medium Density"
  oval 0.65x0.22 smd paste-0.02 mask+0.062: 1(-0.825,0.6) 2(-0.825,0.2) 3(-0.825,-0.2) 4(-0.825,-0.6) 9(0.825,-0.6) 10(0.825,-0.2) 11(0.825,0.2) 12(0.825,0.6)
  oval 0.22x0.65 smd paste-0.02 mask+0.062: 5(-0.6,-1.225) 6(-0.2,-1.225) 7(0.2,-1.225) 8(0.6,-1.225) 13(0.6,1.225) 14(0.2,1.225) 15(-0.2,1.225) 16(-0.6,1.225)
  silkscreen extent -1.45,-1.4 1,1.4, body extent -0.91,-1.31 0.91,1.31, height 0.55
XTAL_3215 [mm] "XTAL SMD 3.2 x 1.5 mm"
  rect 1x1.8 smd: 1(-1.25,0) 2(1.25,0)
  silkscreen extent -0.6,-0.75 0.6,0.75, body extent -1.6,-0.75 1.6,0.75, height 0.81

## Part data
Bat1: library part "Bat Holder CR1025 SMD", "Bat Holder CR1025 SMD"
C1 C2: library part C1206-2µ2, "Capacitor, X7R, ±10%"
C3: library part C0805-220n, "Capacitor, X7R, ±10%"
C4 C5 C6 C7 C8 C9 C10 C12 C13 C14 C15 C17 C18 C22 C23 C26 C27 C28 C29 C30 C31 C32 C33 C34 C35: library part C0402-100n, "Capacitor, X7R, ±10%"
C11: library part C0402-180p, "Capacitor, NP0, ±5%"
C16: library part C0805-10µ, "Capacitor, X5R, ±10%"
C19: library part C0603-1µ0, "Capacitor, X7R, ±10%"
C20 C21: library part C0402-12p, "Capacitor, NP0, ±2%"
C24 C25: library part C0402-18p, "Capacitor, NP0, ±5%"
Fid1 Fid2: library part Fid-Mark, "Fiducial Mark"
LOGO1: "Nordic Logo, medium size"
P1 P3: library part "Pin List 1x8 SMD", "Pin List 1x8, 2.54mm (100mil), SMD"
P2: library part "Pin List 1x6 SMD", "Pin List 1x6, 2.54mm (100mil), SMD"
P4: library part "Pin List 1x10 SMD", "Pin List 1x10, 2.54mm (100mil), SMD"
P5: library part "Socket 2x3 SMD Bottom", "Socket 2x3, 2.54mm (100mil), SMD"
P6: library part "Molex 51441-1072", "FFC/FPC Connector, Right-Angle, SMD, ZIF, Bottom Contacts, 10-way, Gold"
Q1 Q2 Q3 Q4 Q5: "Fairchild, FDG6321C, Dual N & P Channel Digital FET"
R1 R18: library part R0402-10k, "Resistor, ±1%, 0.063W"
R2 R4 R7 R8 R14: library part R0402-N.C., "Not mounted"
R3 R5 R6 R11 R13 R15 R16 R17: library part R0402-1M0, "Resistor, ±1%, 0.063W"
R9: library part R0402-10M, "Resistor, ±1%, 0.063W"
R10: library part R0402-330k, "Resistor, ±1%, 0.063W"
R12: library part R0402-1K0, "Resistor, ±1%, 0.063W"
R19: library part R0402-100, "Resistor, ±1%, 0.063W"
SB7 SB11 SB13 SB14 SB15 SB16 SB17 SB18 SB20 SB22 SB23 SB24 SB25 SB26 SB27 SB28: library part "Solderbridge Shorted", "Shorted Solderbridge"
SW1: library part CAS-D20TA, "SMD slide Switch 2xSPDT"
SW2: library part CJS-1200TA, "SMD slide Switch (ON-ON)"
TP1 TP2 TP3 TP4 TP5 TP6 TP7 TP8 TP9 TP10 TP11 TP12 TP13 TP14 TP15 TP16 TP17 TP18 TP19 TP20 TP21 TP22 TP23 TP24 TP25 TP26 TP27 TP28 TP29 TP30 TP31 TP32 TP33 TP34 TP35 TP36 TP37 TP38 TP41 TP42: library part TP_SMD_Ø1.0MM, "1.0mm circular SMD testpad"
U1: library part SN74LVC1G175DBVR, "Single D-Type Flip-Flop With Asynchronous Clear"
U2: "IC MULTI CONFG 3.3V 30MA SOT23-6"
U3: library part FXMA108BQX, "8-bit bidirectional voltage-level translator with auto-direction sensing"
U4: library part 23LCV512-I/ST, "512 kbit SPI Serial SRAM with Battery Backup and SDI Interface"
U5 U12: library part NX3L4053HR, "Triple low-ohmic single-pole double-throw analog switch"
U6: "12-Stage Ripple Carry Binary Counter"
U7: "IC GPIO EXPANDER I2C 16CH 28QFN"
U8: library part ADG704BRMZ, "IC MUX 4-CH 1.8/5.5V 10MSOP"
U9: "Dual Inverter"
U10: "Dual 4-bit binary ripple counter"
U11: library part 74LVC3GU04DC,125, "Triple Inverter"
U13: library part NX3DV2567GU, "Low-ohmic four-pole double-throw analog switch"
U14 U15 U16 U17: "Data / Audio Low-Voltage Dual DPDT Analog Switch"
U18 U19 U20 U21: library part 74LVC1G17SE, "Single schmitt-trigger buffer with standard push-pull output"
X2: library part "XTAL_FC-135 32.768k", "EPSON TOYOCOM - FC-135 32.768KHZ ±20PPM,9.0PF - CRYSTAL, SM, WATCH"
X3: library part XTAL_SMD5032_8MHz_18pF_TXC, "XTAL SMD 5032, 8MHz, Cl=18pF, Tol: ±30ppm, Stab: ±30ppm"

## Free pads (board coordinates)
  oval 530.32x157.48 hole 118.11 slot 490.94 at 0 deg: 0(1400,330)
  round 126 hole 126: 1(550,130) 1(600,2030) 1(2600,330) 1(2600,1430)

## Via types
v1: diameter 24, hole 12, Top Layer to Bottom Layer, tented both sides, 544 vias

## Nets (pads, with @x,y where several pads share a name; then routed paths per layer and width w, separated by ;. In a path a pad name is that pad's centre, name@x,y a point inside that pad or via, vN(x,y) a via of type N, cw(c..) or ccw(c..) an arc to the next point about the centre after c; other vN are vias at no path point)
1C\P\: U10.1 | length 36.4
  Bottom Layer w15: U10.1@1527.84,1288.06 1527.84,1324.47
1MHZ: SB11.2 U10.9 | length 55.6
  Bottom Layer w6: SB11.2@1417.6,1179 1423.46,1184.86 1428.23,1189.63 U10.9@1468.79,1189.63
1MR: U10.2 | length 36.4
  Bottom Layer w13: U10.2@1567.21,1268.37 1603.63,1268.37
1Q0: U10.3 | length 36.4
  Bottom Layer w13: U10.3@1567.21,1248.68 1603.63,1248.68
1Q1: U10.4 | length 36.4
  Bottom Layer w13: U10.4@1567.21,1229 1603.63,1229
1Q2: U10.5 | length 36.4
  Bottom Layer w13: U10.5@1567.21,1209.31 1603.63,1209.31
1Q3: U10.6 | length 36.4
  Bottom Layer w13: U10.6@1567.21,1189.63 1603.63,1189.63
2MHZ: SB10.2 U10.10 | length 59.3
  Bottom Layer w6: SB10.2@1417.6,1229 1423.46,1223.14 1437.29,1209.31 U10.10@1468.79,1209.31
4MHZ: SB9.2 U10.11 | length 80.5
  Bottom Layer w6: SB9.2@1417.6,1279 1417.6,1265.1 1417.6,1264.4 1453,1229 U10.11@1468.79,1229
8HZ: U6.1 U8.2 | length 462.4
  Top Layer w6: v1(2054.95,764.05) 2063.95,773.05 2098.25,773.05 2102.3,769 v1(2225,769)
  Bottom Layer w6: U8.2@2044.26,694.05 2044.26,753.36 v1(2054.95,764.05) ; v1(2225,769) 2225,788.06 2300.56,863.61 U6.1@2387.13,863.61
16HZ: U6.15 U8.9 | length 164.2
  Bottom Layer w6: U8.9@2044.26,855.47 2044.26,819 2048.29,814.97 2076.97,814.97 2100.02,838.02 U6.15@2160.76,838.02
32HZ: U6.14 U8.4 | length 241.2
  Bottom Layer w6: U8.4@2004.89,694.05 2005.95,695.1 2005.95,757.05 2051.87,802.97 2081.94,802.97 2091.4,812.43 U6.14@2160.76,812.43
64HZ: U6.12 U8.7 | length 252.4
  Top Layer w6: v1(2003.95,785.35) 2046.25,743.05 2101.05,743.05 v1(2106,748)
  Bottom Layer w6: v1(2003.95,785.35) 2004.89,786.29 U8.7@2004.89,855.47 ; v1(2106,748) 2119.25,761.25 U6.12@2160.76,761.25
500KHZ: SB12.2 U10.8 | length 105.5
  Bottom Layer w6: SB12.2@1419.6,1129 1460.54,1169.94 U10.8@1508.16,1169.94
A0: P2.1 TP41.1 | length 267.7
  Bottom Layer w6: P2.1@2000,183 TP41.1@2000,340
  Bottom Layer w15: P2.1@2000,72.32 P2.1@2000,183
A1: P2.2 TP42.1 | length 267.7
  Bottom Layer w6: P2.2@2100,179 TP42.1@2100,340
  Bottom Layer w15: P2.2@2100,72.32 P2.2@2100,179
A2: SB14.1 U14.5 | length 726.8
  Top Layer w6: v1(1630.77,631.23) 1688,574 v1(1688,563)
  Bottom Layer w6: v1(1630.77,631.23) U14.5@1630.77,655.38 ; v1(1688,563) 1688,538 1822,404 2156,404 SB14.1@2200,360
A3: SB15.1 U14.1 | length 778.3
  Top Layer w6: v1(1702.62,616.62) 1718,601.24 v1(1718,563)
  Bottom Layer w6: v1(1702.62,616.62) U14.1@1702.62,646.52 ; v1(1718,563) 1718,524.97 1826.97,416 2244,416 SB15.1@2300,360
A4: SB16.1 U14.9 | length 1060.8
  Top Layer w6: v1(1642,757) 1652,757 1730,679 1730,581 v1(1748,563)
  Bottom Layer w6: v1(1642,757) 1655.38,743.62 U14.9@1655.38,711.48 ; v1(1748,563) 1748,511.94 1831.94,428 2332,428 SB16.1@2400,360
A5: SB17.1 U14.13 | length 1072.6
  Top Layer w6: v1(1727.23,736.77) 1727.23,698.74 1742,683.97 1742,599 v1(1778,563)
  Bottom Layer w6: U14.13@1727.23,702.62 v1(1727.23,736.77) ; v1(1778,563) 1778,498.91 1836.91,440 2420,440 SB17.1@2500,360
ADDR0: SW1.2 U7.26 | length 974.2
  Top Layer w6: v1(1913,938) 1913,969.67 1951.33,1008 2000.12,1008 2020.43,1028.31 2216.31,1028.31 2282,1094 v1(2282,1303)
  Bottom Layer w6: v1(1913,938) 1913,969.67 1951.33,1008 1969.6,1008 1994.25,1032.65 U7.26@1994.25,1049.21 ; v1(2282,1303) 2319,1340 SW1.2@2319,1445.17
ADDR1: SW1.5 U7.10 | length 581.4
  Bottom Layer w6: U7.10@1994.25,1200.79 1994.25,1322.25 2182,1510 2279,1510 2319,1550 SW1.5@2319,1590.83
AREF: Q5.2 R18.1 SB6.1 U13.2 U14.2 U14.10 U15.2 U15.10 U16.2 U16.10 U17.2 U17.10 | length 5765.3
  Top Layer w6: v1(506,1942) 534,1914 534,1835.87 v1(551.87,1818) 577.37,1792.5 v1(622.5,1792.5) ; v1(604,947) 603,948 603,983 646,1026 646,1067 v1(662,1083) ; v1(874,1698) 874,1654 899,1654 v1(965,1588) ; v1(1353,1112) v1(1386,1079) ; v1(1619,1043) 1706,956 v1(1749,956)
  Bottom Layer w6: U17.10@168.87,1680.52 168.87,1692.09 153.13,1707.84 U17.2@153.13,1745.48 153.13,1810.82 196,1853.7 222.79,1853.7 297.59,1928.5 420.19,1928.5 R18.1@448.69,1957 491,1957 v1(506,1942) ; U16.10@392.87,1680.52 392.87,1692.09 377.13,1707.84 U16.2@377.13,1745.48 377.13,1767.1 414.03,1804 537.87,1804 v1(551.87,1818) ; v1(604,947) 527,947 478,898 478,806.24 ; U15.10@628.87,1680.52 628.87,1692.09 613.13,1707.84 U15.2@613.13,1745.48 613.13,1783.13 v1(622.5,1792.5) 638,1808 842,1808 900,1750 ; v1(662,1083) 662,1084.7 695.3,1118 708.03,1118 732.03,1142 814.03,1142 875,1202.97 v1(875,1653) ; U13.2@689.52,806.13 688.77,806.88 478.88,806.88 478.76,807 478,806.24 ; v1(874,1698) 874,1724 900,1750 ; SB6.1@940,1750 926.1,1750 900,1750 ; v1(965,1588) 965,1522.3 947,1504.3 947,1414.97 977,1384.97 977,1360.97 1076.97,1261 1145.7,1261 1229,1177.7 1229,1147 1264,1112 v1(1353,1112) ; Q5.2@1011,356.4 1011,329 997,315 970,315 908,253 534,253 478,309 478,806.24 ; v1(1386,1079) 1434.31,1030.69 1606.69,1030.69 v1(1619,1043) ; U14.2@1686.87,646.52 1686.87,682.82 1671.13,698.57 U14.10@1671.13,711.48 1671.13,759.65 1739.69,828.21 1739.69,946.69 v1(1749,956)
"D0 (RX)": P3.1 TP31.1 | length 287.7
  Bottom Layer w6: TP31.1@2500,1800 P3.1@2500,1972.32
  Bottom Layer w15: P3.1@2500,1972.32 P3.1@2500,2087.68
"D1 (TX)": P3.2 TP32.1 | length 287.7
  Bottom Layer w6: TP32.1@2400,1800 P3.2@2400,1972.32
  Bottom Layer w15: P3.2@2400,1972.32 P3.2@2400,2087.68
D2: SB26.1 U15.15 | length 1957.6
  Bottom Layer w6: U15.15@572.77,1720.87 550.13,1720.87 533,1738 533,1767 546,1780 566,1780 606,1820 945.15,1820 1077.15,1688 2208,1688 SB26.1@2300,1780
D3: SB18.1 U15.11 | length 1718.8
  Top Layer w6: v1(2165,1658) v1(2165,1713)
  Bottom Layer w6: U15.11@613.13,1680.52 613.13,1668.95 623.35,1658.72 673,1658.72 690.28,1676 2147,1676 v1(2165,1658) ; v1(2165,1713) 2165,1736 2200,1771 SB18.1@2200,1780
D4: SB20.1 U16.15 | length 2089.7
  Top Layer w6: v1(1181,1759) 1181,1763 1198,1780 1234,1780 1257,1757 v1(1257,1709)
  Bottom Layer w6: U16.15@336.77,1720.87 321,1720.87 314.13,1727.75 314.13,1796.1 398.03,1880 970,1880 1102,1748 1170,1748 v1(1181,1759) ; v1(1257,1709) 1266,1700 2038,1700 2100,1762 SB20.1@2100,1780
D5: P3.6 TP34.1 | length 287.7
  Bottom Layer w6: TP34.1@2000,1800 P3.6@2000,1972.32
  Bottom Layer w15: P3.6@2000,1972.32 P3.6@2000,2087.68
D6: P3.7 TP35.1 | length 287.7
  Bottom Layer w6: TP35.1@1900,1800 P3.7@1900,1972.32
  Bottom Layer w15: P3.7@1900,1972.32 P3.7@1900,2087.68
D7: P3.8 TP36.1 | length 287.7
  Bottom Layer w6: TP36.1@1800,1800 P3.8@1800,1980
  Bottom Layer w15: P3.8@1800,1980 P3.8@1800,2087.68
D8: P4.1 TP33.1 | length 288.3
  Bottom Layer w6: TP33.1@1640,1800 1640.75,1800.75 1640.75,1864.92 1640,1865.67 P4.1@1640,1972.32
  Bottom Layer w15: P4.1@1640,1972.32 P4.1@1640,2087.68
D9: SB7.1 U16.3 | length 1282.7
  Bottom Layer w6: U16.3@392.87,1745.48 392.87,1765.87 405,1778 ; 405.03,1778 419.03,1792 561.03,1792 601.03,1832 950.12,1832 1082.12,1700 1217.61,1700 1247.61,1730 1490,1730 SB7.1@1540,1780
"D10 (SS)": SB25.1 U13.13 U16.7 | length 2749.7
  Top Layer w6: v1(447,1759) v1@447,1827 ; v1(776,1097) 776,1041.7 813,1004.7 v1(813,950) ; v1(1350,1643) v1(1350,1751)
  Bottom Layer w6: U16.7@433.23,1705.13 449.13,1705.13 456,1712 456,1750 v1(447,1759) ; v1(448,1827) 520,1827 537,1844 955.09,1844 1087.09,1712 1212.64,1712 1242.64,1742 1341,1742 v1(1350,1751) 1379,1780 SB25.1@1440,1780 ; U13.13@745.62,765.77 761.77,765.77 803,807 803,940 v1(813,950) ; v1(776,1097) 785,1106 828.94,1106 911,1188.06 911,1583 950,1622 1329,1622 v1(1350,1643)
"D11 (MOSI)": SB24.1 U13.9 U16.11 | length 2683.4
  Top Layer w6: v1(387,1812) 368,1793 368,1669 v1(388,1649) ; v1(734,1097) 734,971 v1(746,959) ; v1(1304,1643) v1(1304,1763)
  Bottom Layer w6: U16.11@377.13,1680.52 377.13,1659.87 v1(388,1649) ; v1(387,1812) 431,1856 960.06,1856 1092.06,1724 1207.67,1724 1244.22,1760.55 1320.55,1760.55 SB24.1@1340,1780 ; v1(734,1097) 755,1118 823.97,1118 899,1193.03 899,1587.97 945.03,1634 1295,1634 v1(1304,1643) ; v1(746,959) 746,928 758.95,915.05 758.95,842.09 U13.9@754.48,837.62
"D12 (MISO)": SB23.1 U17.3 | length 1206.7
  Bottom Layer w6: U17.3@168.87,1745.48 168.87,1765.87 181,1778 ; 181.03,1778 295.03,1892 974.97,1892 1106.97,1760 1151.91,1760 1171.91,1780 SB23.1@1240,1780
"D13 (SCK)": SB22.1 U13.5 U17.7 | length 2476.9
  Top Layer w6: v1(197,1825) 197,1785 v1(223,1759) ; v1(672,958) 678,952 708.7,952 722,965.3 722,1079 v1(704,1097) ; v1(1087,1655) 1100,1668 v1(1100,1797)
  Bottom Layer w6: v1(197,1825) 211.06,1825 290.06,1904 979.94,1904 1103.94,1780 SB22.1@1140,1780 ; U17.7@209.23,1705.13 225.13,1705.13 232,1712 232,1750 v1(223,1759) ; v1(672,958) 672,904 698.38,877.62 U13.5@698.38,862.23 ; v1(704,1097) 737,1130 819,1130 887,1198 887,1592.94 949.06,1655 v1(1087,1655)
EXTCOMIN_EXT_3V3: U5.3 U7.14 | length 1201.7
  Top Layer w6: v1(1765,1082) 1767.31,1084.31 1767.31,1198.31 1840,1271 2073,1271 2081,1263 v1@2081,1202.57
  Bottom Layer w6: U5.3@1199.55,904.13 1214,904.13 1233.13,885 1315.06,885 1448.74,1018.69 1627.99,1018.69 1682.3,1073 1756,1073 v1(1765,1082) ; U7.14@2057.24,1200.79 v1(2079.21,1200.79)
